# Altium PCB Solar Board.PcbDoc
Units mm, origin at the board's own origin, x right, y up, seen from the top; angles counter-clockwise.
Board outline 65 x 65 mm, 2 copper layers (Top Layer, Bottom Layer), stack 1.57 mm thick; 51 components, 34 nets, 176 pads, 29 vias.
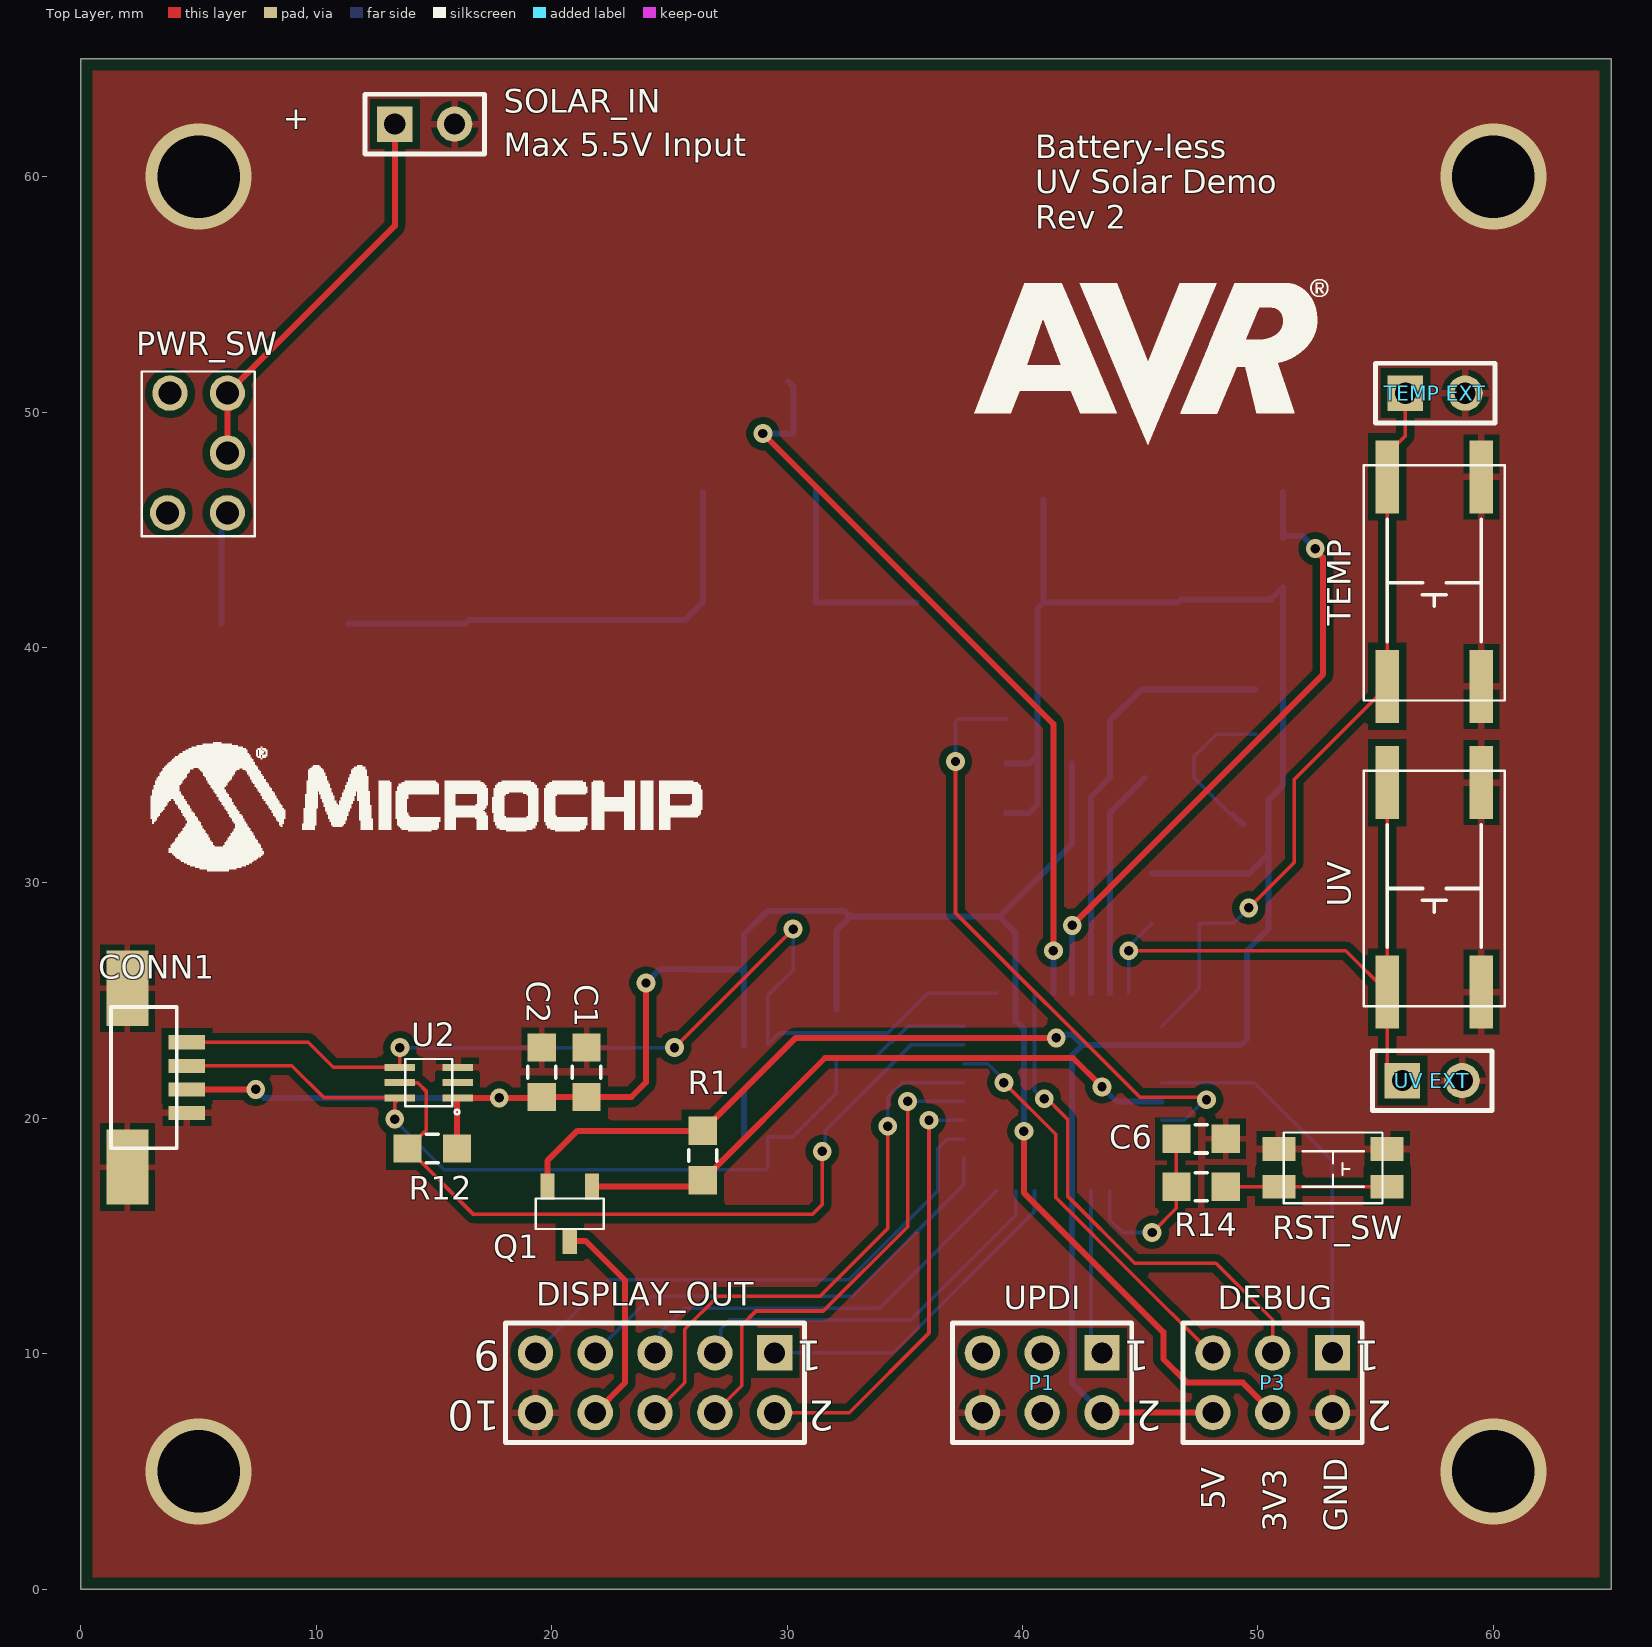
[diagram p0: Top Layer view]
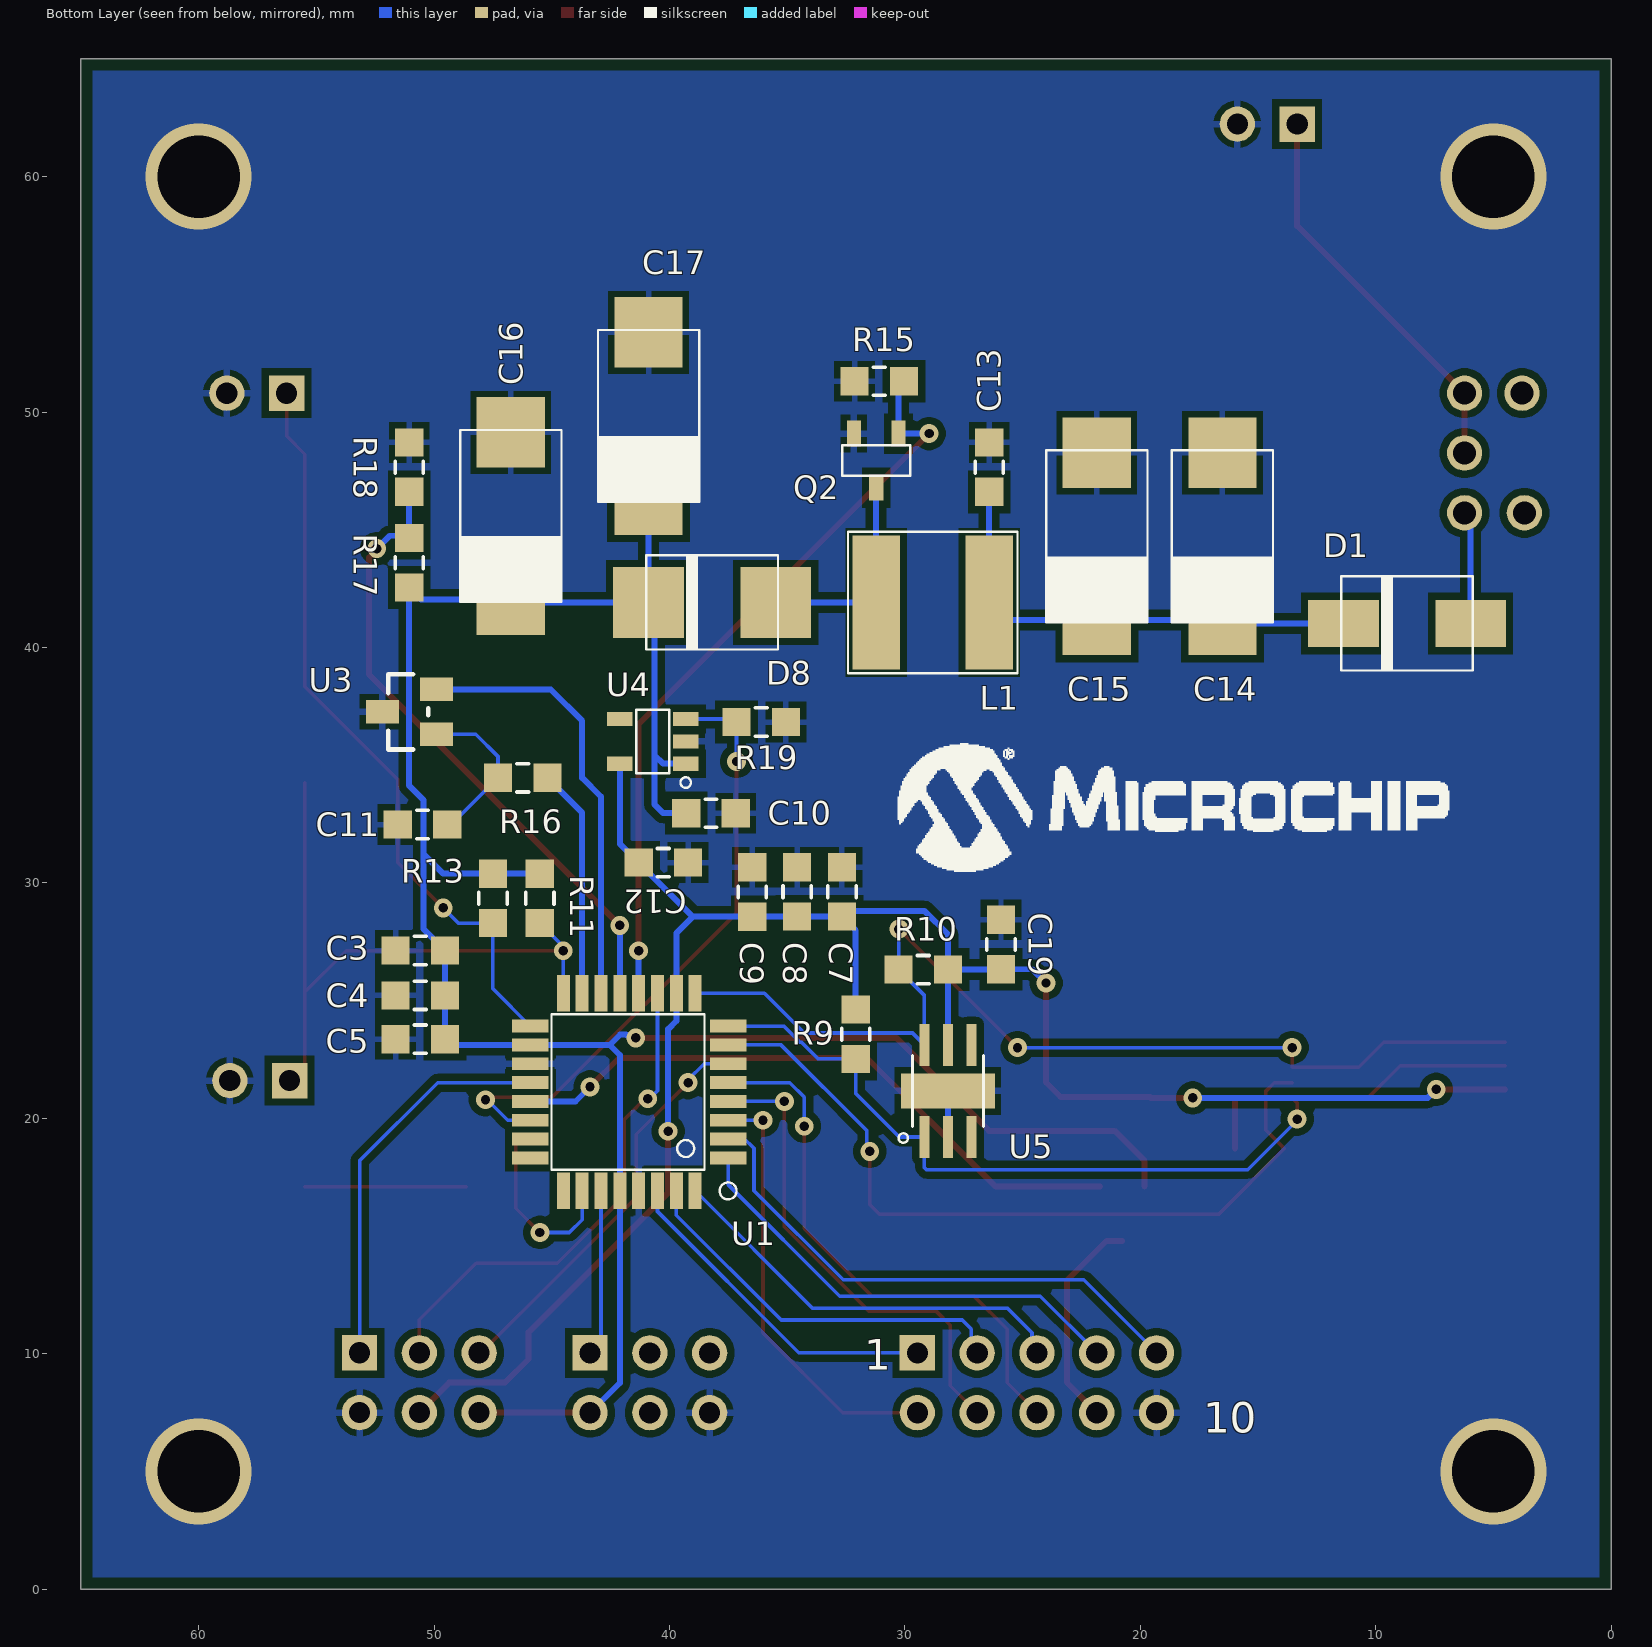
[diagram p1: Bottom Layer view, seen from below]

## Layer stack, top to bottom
Top Solder: solder mask 0.01, Solder Resist, Dk 3.5
Top Layer: signal copper 0.035
Dielectric1: core 1.5, FR-4, Dk 4.8
Bottom Layer: signal copper 0.035
Bottom Solder: solder mask 0.01, Solder Resist, Dk 3.5

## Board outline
0,0 0,65 65,65 65,0

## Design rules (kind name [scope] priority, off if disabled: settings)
AcuteAngle [All] p1 off: minimum=9.00000000000000E+0001 checktracksonly=TRUE
BoardOutlineClearance BoardOutlineClearance_Overlay [OnLayer('Top Overlay','Bottom Overlay')] p1: gap=0.2 ignorepadtopadclearanceinfootprint=FALSE
BoardOutlineClearance [All] p2: gap=0.5 ignorepadtopadclearanceinfootprint=FALSE
Clearance "Net to Polygon 0.5mm" [InNet('your net here') vs (IsRegion)] p1: gap=0.152 ignorepadtopadclearanceinfootprint=FALSE
Clearance "Poly 0.3mm" [(IsRegion)] p2: gap=0.3 ignorepadtopadclearanceinfootprint=FALSE
Clearance [All] p3: gap=0.25 ignorepadtopadclearanceinfootprint=TRUE
ComponentClearance ComponentClearance_ignore [HasFootprint('NET_TIE_0.5mm')] p1: gap=0 collisioncheckmode=3 verticalgap=0 showdistances=FALSE
ComponentClearance [All] p2: gap=0.2 collisioncheckmode=3 verticalgap=0.2 showdistances=FALSE
DiffPairsRouting [All] p1: maxlimit=0.25 minlimit=0.25 mostfreqgap=0.25 toplayer_minwidth=0.25 toplayer_maxwidth=0.25 toplayer_prefwidth=0.25 bottomlayer_minwidth=0.25 bottomlayer_maxwidth=0.25 bottomlayer_prefwidth=0.25 maxuncoupledlength=12.7
FabricationTestPointUsage TestPointUsage [All] p1: valid=0 allowmultiple=FALSE
FabricationTestpoint Testpoint [All] p1: side=3 testpointundercomponent=TRUE minsize=1.016 maxsize=2.54 preferedsize=1.524 minholesize=0 maxholesize=1.016 preferedholesize=0.813 testpointgrid=0.025 allowsidetop=TRUE allowsidebottom=TRUE usegrid=TRUE gridtolerance=0
HoleSize [All] p1: absolutevalues=TRUE maxlimit=6 minlimit=0.254 maxpercent=80.000 minpercent=20.000
HoleToHoleClearance [All] p1: gap=0.127 allowstackedmicrovias=FALSE
MinimumAnnularRing [All] p1: minimumring=0.127
MinimumSolderMaskSliver [All] p1: minsoldermaskwidth=0.102
PasteMaskExpansion PasteMaskExpansion_DNP [IsPad AND HasCompParameterValue('Populated','DNP')] p1: expansion=-5
PasteMaskExpansion [All] p2: expansion=0
PlaneClearance PlaneClearance_pads [IsPad] p1: clearance=0.3
PlaneClearance PlaneClearance_drill [IsObjectKind('Hole')] p2: clearance=0.4
PlaneConnect PlaneConnect_full [IsVia] p1: planeconnectstyle=Direct reliefexpansion=0.5 reliefentries=4 reliefconductorwidth=0.3 reliefairgap=0.3
PlaneConnect [All] p2: planeconnectstyle=Relief reliefexpansion=0.3 reliefentries=4 reliefconductorwidth=0.25 reliefairgap=0.25
PolygonConnect PolygonConnect_0.7 [IsNamedPolygon('0.7mm') vs (InPadClass('All Pads'))] p1: connectstyle=Relief reliefconductorwidth=0.7 reliefentries=4 polygonreliefangle="90 Angle" airgapwidth=0.25
PolygonConnect PolygonConnect_0.5 [IsNamedPolygon('0.5mm') vs (InPadClass('All Pads'))] p2: connectstyle=Relief reliefconductorwidth=0.5 reliefentries=4 polygonreliefangle="90 Angle" airgapwidth=0.25
PolygonConnect PolygonConnect_full [All vs IsVia or IsNamedPolygon('full')] p3: connectstyle=Direct reliefconductorwidth=0 reliefentries=4 polygonreliefangle="90 Angle" airgapwidth=0.254
PolygonConnect [All] p4: connectstyle=Relief reliefconductorwidth=0.3 reliefentries=4 polygonreliefangle="90 Angle" airgapwidth=0.25
RoutingCorners [All] p1: cornerstyle=45-Degree minsetback=2.5 maxsetback=2.5
RoutingVias [All] p1: holewidth=0.4 width=0.8 viastyle="Through Hole" minholewidth=0.3 minwidth=0.7 maxholewidth=1.6 maxwidth=2.5
SMDToCorner [All] p1: distance=39370
ShortCircuit [IsNet] p1: allowed=FALSE
SilkToSilkClearance [All] p1: silktosilkclearance=0.076
SilkToSolderMaskClearance SilkscreenOverComponentPads [IsPad] p1 off: minsilkscreentomaskgap=0.2 clearancetoexposedcopper=TRUE
SolderMaskExpansion SolderMaskExpansion_Component_Via [IsComponentVia] p1: expansion=0.075 istentingtop=FALSE soldermaskfromhole=TRUE
SolderMaskExpansion [All] p2: expansion=0.1 istentingtop=FALSE
UnRoutedNet [All] p1: checkbadconnections=TRUE
ViasUnderSMD [All] p1: allowed=FALSE
Width "Power Trace Width" [InNetClass('Power')] p1: maxlimit=7 minlimit=0.254 preferedwidth=0.254 minimp=50.000000 maximp=50.000000 favimp=50.000000
Width "Default Width" [InNetClass('All Nets')] p2: maxlimit=0.254 minlimit=0.152 preferedwidth=0.152 minimp=50.000000 maximp=50.000000 favimp=50.000000
15 further rules are at their usual default settings.

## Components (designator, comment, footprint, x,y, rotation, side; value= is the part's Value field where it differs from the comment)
C1 "Capacitor" 0805 21.479,20.901 r90 top
C2 "Capacitor" 0805 19.574,20.901 r90 top
C3 "Capacitor" 0805 49.535,27.125 r0 bottom
C4 "Capacitor" 0805 49.535,25.22 r0 bottom
C5 "Capacitor" 0805 49.535,23.361 r0 bottom
C6 "Capacitor" 0805 46.534,19.126 r0 top
C7 "Capacitor" 0805 32.673,28.567 r90 bottom
C8 "Capacitor" 0805 34.578,28.567 r90 bottom
C9 "Capacitor" 0805 36.483,28.561 r90 bottom
C10 "Capacitor" 0805 39.287,32.96 r180 bottom
C11 "Capacitor" 0805 49.439,32.477 r0 bottom
C12 "Capacitor" 0805 41.309,30.861 r180 bottom
C13 "Capacitor" 0805 26.416,46.609 r90 bottom
C14 "Polarized Capacitor" 2917 16.51,41.172 r90 bottom
C15 "Polarized Capacitor" 2917 21.844,41.172 r90 bottom
C16 "Polarized Capacitor" 2917 46.736,42.037 r90 bottom
C17 "Polarized Capacitor" 2917 40.887,46.286 r90 bottom
C19 "Capacitor" 0805 25.916,26.33 r90 bottom
CONN1 "STEMMA-QT" JST-ST 1.977,24.526 r270 top
D1 "Schottky" DO-215AB#1 5.969,41.021 r0 bottom
D8 "Schottky" DO-215AB#2 35.487,41.91 r0 bottom
DISPLAY_OUT "Header 5X2" HDR2X5 29.469,10.033 r180 top
L1 "Inductor" "6mm x 6mm Inductor" 26.416,41.91 r0 bottom value="330 uH"
P1 "Header 3X2" HDR2X3 43.373,10.033 r180 top
P3 "Header 3X2" HDR2X3 53.164,10.037 r180 top
PWR_SW "SPDT Slide" "CST11T2CR (SPST)" 3.683,45.72 r0 top
Q1 "PMOS Transistor" SOT-23 21.717,17.094 r180 top
Q2 "NMOS Transistor" SOT-23 30.266,49.086 r0 bottom
R1 "Resistor" 0805 26.416,17.367 r90 top value=100k
R9 "Resistor" 0805 32.089,22.52 r90 bottom value=10k
R10 "Resistor" 0805 30.269,26.315 r180 bottom value=10k
R11 "Resistor" 0805 45.505,30.391 r270 bottom value=DNP
R12 "Resistor" 0805 13.877,18.715 r0 top value=10k
R13 "Resistor" 0805 47.498,30.391 r270 bottom value=DNP
R14 "Resistor" 0805 46.534,17.094 r0 top value=330
R15 "Resistor" 0805 32.136,51.308 r180 bottom value=100k
R16 "Resistor" 0805 47.284,34.46 r180 bottom value=200
R17 "Resistor" 0805 51.054,44.645 r270 bottom value=100k
R18 "Resistor" 0805 51.054,48.709 r270 bottom value=10k
R19 "Resistor" 0805 35.052,36.83 r0 bottom value=100k
RST_SW "SPST Switch" KMR7 50.89,17.094 r0 top
SOLAR_IN "Header 2" HDR1X2 13.335,62.23 r0 top
TEMP "SPST Switch" KSC4 55.49,47.244 r270 top
"TEMP EXT" "Header 2" HDR1X2 56.261,50.8 r0 top
U1 "AVR64DD32" TQFP-32 37.509,18.315 r90 bottom
U2 "LTR390" "Extended QFN-6" 13.877,20.865 r90 top
U3 "MCP9700(A)_1(A) TO-92-3_SOT-23-3" SOT-23-3 51.047,37.265 r90 bottom value=MCP9700A
U4 "MCP1711" SOT23-5 39.309,35.06 r90 bottom
U5 "HTU21D(F) Humidity Sensor" "HTU21D(F) Extended Package" 28.169,21.16 r90 bottom
UV "SPST Switch" KSC4 55.49,34.26 r270 top
"UV EXT" "Header 2" HDR1X2 56.134,21.6 r0 top

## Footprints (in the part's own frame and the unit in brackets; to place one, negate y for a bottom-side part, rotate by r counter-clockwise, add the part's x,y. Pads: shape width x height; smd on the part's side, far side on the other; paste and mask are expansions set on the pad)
"6mm x 6mm Inductor" [mm] "For ASPI-6045S-331M-T"
  rect 2x5.7 smd: 1(0,0) 2(4.8,0)
  silkscreen extent -1.2,-3 6,3
0805 [mm] "Non-Polarized"
  rect 1.2x1.2 smd: 1(0,0) 2(2.1,0)
  silkscreen extent 0.8,-0.6 1.3,0.6
2917 [mm] "2917 SMD Package"
  rect 3x2.9 smd: A(0,0) K(7.1,0)
  silkscreen extent -0.1,-2.15 7.2,2.15
"CST11T2CR (SPST)" [mm] "SPST Switch Footprint for CST11T2CR"
  round 1.5 hole 0.98: 1(0,0) 3(0.1,5.08) 4(2.54,5.08) 5(2.54,2.54) 6(2.54,0)
  silkscreen extent -1.1,-1 3.7,6
DO-215AB#1 [mm]
  rect 3x2 smd: A(0,0) K(5.4,0)
  silkscreen extent -0.1,-2 5.5,2
DO-215AB#2 [mm]
  rect 3x3 smd: A(0,0) K(5.4,0)
  silkscreen extent -0.1,-2 5.5,2
"Extended QFN-6" [mm]
  rect 0.3x1.3 smd: 1(0,-2.125) 2(0.65,-2.125) 3(1.3,-2.125) 4(1.3,0.325) 5(0.65,0.325) 6(0,0.325)
  silkscreen extent -0.7,-2.2 1.65,0.1
HDR1X2 [mm] "Connector; Header; 2 Position"
  rect 1.5x1.5 hole 0.9: 1(0,0)
  round 1.5 hole 0.9: 2(2.54,0)
  silkscreen extent -1.27,-1.27 3.81,1.27
HDR2X3 [mm] "Connector; Header; 3x2 Position"
  rect 1.5x1.5 hole 0.9: 1(0,0)
  round 1.5 hole 0.9: 2(0,2.54) 3(2.54,0) 4(2.54,2.54) 5(5.08,0) 6(5.08,2.54)
  silkscreen extent -1.27,-1.27 6.35,3.81
HDR2X5 [mm] "Connector; Header; 5x2 Position"
  rect 1.5x1.5 hole 0.9: 1(0,0)
  round 1.5 hole 0.9: 2(0,2.54) 3(2.54,0) 4(2.54,2.54) 5(5.08,0) 6(5.08,2.54) 7(7.62,0) 8(7.62,2.54) 9(10.16,0) 10(10.16,2.54)
  silkscreen extent -1.27,-1.27 11.43,3.81
"HTU21D(F) Extended Package" [mm] "HTU21D(F) Humidity Sensor with Extended Pads"
  rrect11% 1.8x0.42 smd: 1(-1.955,1) 2(-1.955,0) 3(-1.955,-1) 4(1.955,-1) 5(1.955,0) 6(1.955,1)
  rect 1.5x4 smd paste-2: PAD(0,0)
  silkscreen extent -2.2,-1.5 1.5,2.1, body extent -1.5,-1.5 1.5,1.5, height 1
JST-ST [mm] "Stemma QT Connector"
  rect 0.6x1.55 smd: 1(4.3,2.525) 2(3.3,2.525) 3(2.3,2.525) 4(1.3,2.525)
  rect 3.2x1.8 smd: MECH1(-1,0) MECH2(6.6,0)
  silkscreen extent -0.2,-0.7 5.8,2.1
KMR7 [mm] "SPST Footprint for KMR7 Series SW"
  rect 1.4x1 smd: 1(4.6,1.6) 2(4.6,0) 3(0,0) 4(0,1.6)
  silkscreen extent 0.2,-0.7 4.4,2.3
KSC4 [mm] "Layout for KSC4 Series Pushbuttons (Ex: KSC421G 70SH LFS )"
  rect 3.1x1 smd: 1(0,4) 1(8.9,4) 2(0,0) 2(8.9,0)
  silkscreen extent -0.5,-1 9.5,5
SOT23-5 [mm]
  rect 0.6x1.1 smd: 1(0,0) 2(0.95,0) 3(1.9,0) 4(1.9,2.8) 5(0,2.8)
  silkscreen extent -1.02,-0.22 2.3,2.1
SOT-23 [mm]
  rect 0.6x1.1 smd: 1(0,0) 2(1.9,0) 3(0.95,2.3)
  silkscreen extent -0.5,0.5 2.4,1.8
SOT-23-3 [mm]
  rect 1x1.4 smd: 1(-0.95,-1.15) 2(0.95,-1.15) 3(0,1.15)
  silkscreen extent -1.6,-0.8 1.6,0.9, body extent -1.5,-1.25 1.5,1.25, height 1.09
TQFP-32 [mm]
  rect 0.55x1.55 smd: 1(0,0) 2(0.8,0) 3(1.6,0) 4(2.4,0) 5(3.2,0) 6(4,0) 7(4.8,0) 8(5.6,0) 17(5.6,8.4) 18(4.8,8.4) 19(4,8.4) 20(3.2,8.4) 21(2.4,8.4) 22(1.6,8.4) 23(0.8,8.4) 24(0,8.4)
  rect 1.55x0.55 smd: 9(7,1.4) 10(7,2.2) 11(7,3) 12(7,3.8) 13(7,4.6) 14(7,5.4) 15(7,6.2) 16(7,7) 25(-1.4,7) 26(-1.4,6.2) 27(-1.4,5.4) 28(-1.4,4.6) 29(-1.4,3.8) 30(-1.4,3) 31(-1.4,2.2) 32(-1.4,1.4)
  silkscreen extent -1.76,-0.36 6.1,7.5

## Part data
C1 C12: Capacitance=4.7uF
C2 C3 C7 C19: Capacitance=0.1uF
C4 C8: Capacitance=10nF
C5 C6 C9 C11: Capacitance=1uF
C10 C13: Capacitance=10uF
C14 C15 C16 C17: Capacitance=220uF, Rated Voltage=10V
CONN1: library part Stemma-QT, "Used with JST-ST Cables"
D1 D8: Part Number=LSM115JE3/TR13
DISPLAY_OUT: "Header, 5-Pin, Dual row"
L1: Part Number=ASPI-6045S-331M-T
P1 P3: "Header, 3-Pin, Dual row"
PWR_SW: Part Number=CST11T2CR
Q1: library part PMOS, Part Number=SSM3J168F,LF
Q2: library part NMOS, Part Number=DMN3731U-7
RST_SW TEMP UV: library part SPST
SOLAR_IN "TEMP EXT" "UV EXT": "Header, 2-Pin"
U3: library part MIC3211, "MCP97XX", Manufacturer 1=Microchip, Manufacturer Part Number 1=MCP9700AT-E/TT, Operating Temperature="-40C to +125C"
U4: Package=SOT23-5
U5: library part HTU21D

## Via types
v1: diameter 0.8, hole 0.4, Top Layer to Bottom Layer, 25 vias
v2: diameter 4.5, hole 3.5, Top Layer to Bottom Layer, 4 vias

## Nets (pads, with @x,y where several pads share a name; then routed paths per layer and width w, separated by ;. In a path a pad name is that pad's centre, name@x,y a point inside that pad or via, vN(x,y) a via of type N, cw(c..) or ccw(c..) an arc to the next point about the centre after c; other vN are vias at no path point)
"3.3V EN": R19.2 U1.22 U4.3 | length 26.6
  Top Layer w0.152: v1(37.152,35.155) 37.152,28.721 44.972,20.901 47.815,20.901 v1(47.815,20.789)
  Bottom Layer w0.152: v1(37.152,35.155) R19.2 37.282,36.96 U4.3 ; U1.22 46.867,19.915 47.74,20.789 v1(47.815,20.789)
+3.3: C1.1 C2.1 C7.1 C8.1 C9.1 C12.1 C19.1 CONN1.2 P3.4 R9.2 R10.2 R12.2 U1.10 U2.1 U4.5 U5.5 | length 87.8
  Top Layer w0.254: CONN1.2 v1(7.426,21.226) ; R12.2 15.977,20.84 U2.1 v1(17.77,20.865) 19.538,20.865 C2.1 C1.1 23.38,20.901 24.003,21.524 v1(24.003,25.744) ; v1(40.056,19.451) 40.056,16.84 45.984,10.912 45.984,9.772 46.99,8.766 49.355,8.766 P3.4
  Bottom Layer w0.254: v1(7.426,21.226) 7.788,20.865 v1(17.77,20.865) ; v1(24.003,25.744) 24.589,26.33 C19.1 25.931,26.315 R10.2 ; U5.5 R10.2 ; R9.2 32.089,27.983 C7.1 ; v1(40.056,19.451) 40.056,23.784 39.709,24.131 U1.10 39.709,27.861 39.009,28.561 ; U4.5 42.109,31.661 C12.1 39.009,28.561 ; R10.2 28.169,27.81 29.171,28.813 32.427,28.813 C7.1 ; C7.1 C8.1 36.477,28.567 C9.1 39.009,28.561
+5: C3.1 C4.1 C5.1 C10.1 C16.A C17.A D8.K P1.2 P3.6 Q1.2 R1.2 R11.1 R13.1 R17.2 U1.18 U1.28 U4.1 | length 106
  Top Layer w0.254: Q1.2 19.817,18.192 21.092,19.467 R1.2 30.363,23.414 v1(41.432,23.414) ; P1.2 43.376,7.497 P3.6
  Bottom Layer w0.254: C10.1 40.267,32.96 40.64,33.333 40.64,35.433 ; U4.1 40.267,35.06 40.64,35.433 ; C17.A D8.K ; v1(41.432,23.414) 41.536,23.519 41.812,23.519 41.854,23.56 42.091,23.56 42.537,23.115 ; P1.2 42.109,8.757 U1.28 42.109,22.687 42.537,23.115 ; R11.1 R13.1 49.608,30.391 50.454,31.237 ; 40.64,35.433 40.64,41.663 D8.K ; D8.K 46.609,41.91 C16.A 50.546,42.037 R17.2 51.054,34.126 50.454,33.526 50.454,31.237 ; 42.537,23.115 U1.18 49.289,23.115 C5.1 C4.1 C3.1 50.454,28.044 50.454,31.237
"DBG PD1": P3.3 U1.11 | length 21.6
  Top Layer w0.152: v1(40.925,20.826) 41.043,20.826 41.694,20.175 41.912,19.957 41.912,16.696 44.765,13.843 48.215,13.843 50.624,11.434 P3.3
  Bottom Layer w0.152: U1.11 40.509,21.173 40.856,20.826 v1(40.925,20.826)
"FET SW": Q2.1 R15.2 U1.12 | length 32.5
  Top Layer w0.25: v1(28.969,49.086) 41.309,36.746 v1(41.309,27.115)
  Bottom Layer w0.25: v1(28.969,49.086) Q2.1 30.266,51.078 R15.2 ; U1.12 v1(41.309,27.115)
GND: "TEMP EXT.2" "UV EXT.2" C1.2 C2.2 C3.2 C4.2 C5.2 C6.2 C7.2 C8.2 C9.2 C10.2 C11.2 C12.2 C13.2 C14.K C15.K C16.K C17.K C19.2 CONN1.1 CONN1.MECH1 CONN1.MECH2 DISPLAY_OUT.10 P1.6 P3.2 Q2.2 R15.1 R18.1 R19.1 RST_SW.1 RST_SW.4 SOLAR_IN.2 TEMP.1 U1.19 U1.29 U2.3 U3.3 U4.2 U5.2 U5.PAD UV.1 | length 2
  Bottom Layer w0.254: U5.2 U5.PAD
  other v2: 5,5 60,5 5,60 60,60
I\N\T\: R12.1 U1.7 U2.5 | length 33.6
  Top Layer w0.152: U2.5 14.302,21.515 14.677,21.14 14.677,19.515 R12.1 16.677,15.915 31.069,15.915 31.489,16.335 v1(31.489,18.594)
  Bottom Layer w0.152: v1(31.489,18.594) 31.611,18.716 31.611,19.467 35.258,23.115 U1.7
IO0: DISPLAY_OUT.1 U1.30 | length 14.4
  Bottom Layer w0.152: DISPLAY_OUT.1@29.461,10.033 34.502,10.033 40.509,16.04 U1.30
IO1: DISPLAY_OUT.3 U1.31 | length 16.7
  Bottom Layer w0.152: DISPLAY_OUT.3@26.921,10.033 DISPLAY_OUT.3@26.925,10.037 ; DISPLAY_OUT.3 27.179,10.284 27.179,11.046 27.563,11.43 35.253,11.43 39.709,15.886 U1.31
IO2: DISPLAY_OUT.5 U1.32 | length 17.7
  Bottom Layer w0.152: DISPLAY_OUT.5@24.381,10.033 24.599,10.251 24.599,10.883 25.654,11.938 33.932,11.938 U1.32
IO3: DISPLAY_OUT.7 U1.1 | length 19.8
  Bottom Layer w0.152: DISPLAY_OUT.7@21.841,10.033 24.254,12.446 32.766,12.446 37.509,17.189 U1.1
IO4: DISPLAY_OUT.9 U1.2 | length 23
  Bottom Layer w0.152: DISPLAY_OUT.9@19.301,10.033 22.404,13.136 32.617,13.136 36.408,16.926 36.408,18.725 36.599,18.916 36.609,18.916 36.808,19.115 U1.2
IO5: DISPLAY_OUT.2 U1.3 | length 18.5
  Top Layer w0.152: DISPLAY_OUT.2 32.639,7.493 36.027,10.881 v1(36.027,19.915)
  Bottom Layer w0.152: v1(36.027,19.915) U1.3
IO6: DISPLAY_OUT.4 U1.4 | length 20.7
  Top Layer w0.152: DISPLAY_OUT.4@26.921,7.493 28.067,8.639 28.067,11.201 28.677,11.811 31.538,11.811 35.117,15.39 v1(35.117,20.715)
  Bottom Layer w0.152: v1(35.117,20.715) U1.4
IO7: DISPLAY_OUT.6 U1.5 | length 23.5
  Top Layer w0.152: DISPLAY_OUT.6@24.381,7.493 25.654,8.766 25.654,11.041 27.059,12.446 31.399,12.446 34.273,15.32 v1(34.273,19.66)
  Bottom Layer w0.152: v1(34.273,19.66) 34.273,20.901 34.887,21.515 U1.5
"IO COM": Q1.1 R1.1 U1.21 | length 27.2
  Top Layer w0.254: Q1.1 26.143,17.094 R1.1 31.609,22.561 42.143,22.561 v1(43.373,21.331)
  Bottom Layer w0.254: v1(43.373,21.331) 43.989,20.715 U1.21
"LED Anode": DISPLAY_OUT.8 Q1.3 | length 9.2
  Top Layer w0.254: Q1.3 21.435,14.794 23.114,13.115 23.114,8.766 DISPLAY_OUT.8@21.841,7.493
NetC11_1: C11.1 R16.1 U3.1 | length 7.6
  Bottom Layer w0.152: C11.1@48.956,32.96 C11.1 49.267,32.477 R16.1 47.284,35.368 48.23,36.315 U3.1
NetC13_1: C13.1 C14.A C15.A D1.K L1.1 | length 20.1
  Bottom Layer w0.254: D1.K 16.359,41.021 C14.A C15.A 25.678,41.172 L1.1 C13.1
NetD1_A: D1.A PWR_SW.6 | length 4.8
  Bottom Layer w0.254: D1.A 5.969,45.129 6.223,45.383 PWR_SW.6
NetD8_A: D8.A L1.2 Q2.3 | length 9.1
  Bottom Layer w0.254: Q2.3 L1.2 D8.A
NetPWR_SW_COM: PWR_SW.4 PWR_SW.5 SOLAR_IN.1 | length 16.9
  Top Layer w0.254: PWR_SW.5 PWR_SW.4 13.335,57.912 SOLAR_IN.1
NetR14_2: R14.2 RST_SW.2 RST_SW.3 | length 6.9
  Top Layer w0.152: R14.2 RST_SW.3 RST_SW.2
"PWR FB": R17.1 R18.2 U1.13 | length 27
  Top Layer w0.254: v1(42.109,28.194) 52.759,38.844 52.759,43.812 52.435,44.136 v1(52.435,44.196)
  Bottom Layer w0.254: U1.13 v1(42.109,28.194) ; R18.2 R17.1 51.154,44.745 51.886,44.745 v1(52.435,44.196)
R\E\S\E\T\: C6.1 R14.1 U1.26 | length 7.6
  Top Layer w0.152: v1(45.505,15.149) 46.534,16.178 R14.1 C6.1
  Bottom Layer w0.152: U1.26 43.709,15.694 44.254,15.149 v1(45.505,15.149)
SCL: CONN1.4 R10.1 U1.9 U2.4 U5.6 | length 45.2
  Top Layer w0.152: CONN1.4 9.657,23.226 10.719,22.165 U2.4 v1(13.552,23.001) ; v1@25.23,22.987 v1(25.216,23.001) v1(30.251,28.036)
  Bottom Layer w0.152: v1(13.552,23.001) v1(25.216,23.001) ; v1(30.251,28.036) 30.251,26.333 R10.1 29.169,25.215 U5.6 29.677,23.623 34.273,23.623 35.965,25.315 U1.9
SDA: CONN1.3 R9.1 U1.8 U2.6 U5.1 | length 39.8
  Top Layer w0.152: CONN1.3 8.961,22.226 10.323,20.865 U2.6 13.335,20.648 v1(13.335,19.965)
  Bottom Layer w0.152: v1(13.335,19.965) 13.335,19.915 15.435,17.815 29.079,17.815 29.169,17.904 U5.1 30.241,19.205 32.089,21.053 R9.1 33.678,22.52 34.378,23.22 34.439,23.22 35.134,23.915 U1.8
"TCD-A Out (DBG)": P3.1 U1.20 | length 16.8
  Bottom Layer w0.152: U1.20 49.848,21.515 53.164,18.199 P3.1
"TEMP Button": "TEMP EXT.1" R13.2 TEMP.2 U1.17 | length 32
  Top Layer w0.152: v1(49.608,28.934) 51.539,30.865 51.539,34.393 55.49,38.344 55.49,47.244 55.49,48.21 56.261,48.981 56.261,50.8
  Bottom Layer w0.152: U1.17 47.498,25.504 R13.2 48.965,28.291 v1(49.608,28.934)
"TEMP IN": U1.14 U3.2 | length 18.6
  Bottom Layer w0.254: U1.14 42.909,33.659 43.709,34.459 43.709,36.882 45.042,38.215 U3.2
"TEMP PWR": R16.2 U1.15 | length 9.8
  Bottom Layer w0.254: U1.15 43.709,32.985 R16.2
"UART TX": P3.5 U1.6 | length 17.7
  Top Layer w0.152: v1(39.209,21.515) 41.409,19.315 41.409,16.63 41.42,16.63 41.51,16.541 41.51,16.529 44.598,13.441 48.002,10.037 P3.5 ; P3.5@48.292,10.291 P3.5@48.55,10.033
  Bottom Layer w0.152: U1.6 38.527,22.315 39.209,21.633 v1(39.209,21.515)
UPDI: P1.1 U1.27 | length 7.1
  Bottom Layer w0.152: U1.27 42.909,10.497 P1.1
"UV Button": "UV EXT.1" R11.2 U1.16 UV.2 | length 28
  Top Layer w0.152: v1(44.509,27.115) 53.735,27.115 UV.2@55.49,25.36 ; UV.2@55.49,34.26 UV.2@55.49,25.36 ; 56.134,21.6 55.49,22.244 UV.2@55.49,25.36
  Bottom Layer w0.152: U1.16 v1(44.509,27.115) 44.509,27.295 R11.2
pads on no net: P1.3 P1.4 P1.5 PWR_SW.1 PWR_SW.3 U1.23 U1.24 U1.25 U2.2 U4.4 U5.3 U5.4

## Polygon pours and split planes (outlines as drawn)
GND on Bottom Layer "GND_L02_P000" (solid, remove dead copper, pour order 0): 0,0 0,65 65,65 65,0
GND on Top Layer "GND_L01_P001" (solid, remove dead copper, pour order 1): 0,0 0,65 65,65 65,0

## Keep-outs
Keep-Out Layer:
  text "'.Layer_Name'" at 300.5,-158.75 h1.5

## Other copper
Top Layer:
  text "'.ProjectRevisionART'" at 335.678,-158.572 h1.5
  text "'.Layer_Name'" at 300.5,-158.75 h1.5
Bottom Layer:
  text "04-'.ProjectPCBNumber'-R'.ProjectRevisionART'" at 242,-108.5 h1.2
  text ".ProjectRevisionART" at 335.678,-158.572 h1.5
  text ".ProjectRevisionART" at 335.678,-158.572 h1.5
  text "'.ProjectRevisionART'" at 335.678,-158.572 h1.5
  text "'.Layer_Name'" at 300.5,-158.75 h1.5

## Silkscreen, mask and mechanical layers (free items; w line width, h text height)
Top Overlay:
  drawing of 21 lines, arcs and shapes, not listed
  text "+" at 8.582,62.009 h1
  text "Max 5.5V Input" at 17.96,60.858 h1
  text "Battery-less / UV Solar Demo / Rev 2" at 40.547,57.785 h1
  text "UPDI" at 39.209,11.884 h1
  text "DEBUG" at 48.284,11.884 h1
  text "5V" at 48.587,3.375 h1 r90
  text "3V3" at 51.2,2.432 h1 r90
  text "GND" at 53.8,2.432 h1 r90
  text "C" at 251.245,-112.043 h8
  text "1" at 260.096,-112.649 h5
  text "'.ProjectPartNumber'" at 231.5,-113 h1.2
  text "" at 244.245,-113.346 h8
  text "5" at 278.5,-114.194 h8
  text "7" at 288.5,-114.194 h8
  text "0" at 298.5,-114.194 h8
  text "1" at 308.5,-114.194 h8
  text "6" at 268.5,-114.227 h8
  text "2" at 318.5,-114.227 h8
  text "3" at 328.5,-114.227 h8
  text "4" at 338.58,-114.227 h8
  text "ICD" at 284.4,-122 h1.52
  text "M" at 262,-128.5 h10
  text "" at 315,-128.959 h10
  text "" at 294,-128.984 h10
  text "" at 305,-128.984 h10
  text "" at 324,-128.984 h10
  text "" at 335,-128.984 h10
  text "" at 346,-129.159 h10
  text "*h" at 227.7,-130 h7
  text "" at 286,-132 h10
  text "dsPICDEM.net™" at 185.75,-138.75 h3
  text "mTouch®" at 208,-138.75 h3
  text "chipKIT™" at 222.25,-138.75 h3
  text "dsPICDEM™" at 185.5,-144.5 h3
  text "MPLAB®" at 208,-145 h3
  text "dsPIC®" at 222.25,-145 h3
  text "PICDEM.net™" at 185.5,-150.75 h3
  text "PICkit™" at 208.25,-151 h3
  text "PIC®" at 222.25,-151 h3
  text "PICDEM™" at 185.5,-157.25 h3
  text "PICtail™" at 208.25,-157.25 h3
  text "'.ProjectRevisionART'" at 335.678,-158.572 h1.5
  text "'.Layer_Name'" at 300.5,-158.75 h1.5
Bottom Overlay:
  drawing of 15 lines, arcs and shapes, not listed
  text "1" at 31.719,9.326 h1.3
  text "10" at 17.318,6.643 h1.3
  text "'.ProjectRevisionART'" at 335.678,-158.572 h1.5
  text "'.Layer_Name'" at 300.5,-158.75 h1.5
Top Paste:
  text "'.ProjectRevisionART'" at 335.678,-158.572 h1.5
  text "'.Layer_Name'" at 300.5,-158.75 h1.5
Bottom Paste:
  text "'.ProjectRevisionART'" at 335.678,-158.572 h1.5
Top Solder:
  text "'.ProjectRevisionART'" at 335.678,-158.572 h1.5
  text "'.Layer_Name'" at 300.5,-158.75 h1.5
Bottom Solder:
  text "'.ProjectRevisionART'" at 335.678,-158.572 h1.5
NOTES (M1):
  text "ASSEMBLY NOTES:" at 29.4,-109.1 h4
  text "1. ALL COMPONENTS SHALL BE RoHS COMPLIANT." at -4.7,-114.2 h3
  text "2. ALL UNUSED THROUGH HOLE COMPONENT LOCATIONS SHALL BE FREE OF SOLDER." at -4.7,-117.2 h3
  text "3. ALL COMPONENTS SHALL BE MOUNTED FLUSH TO THE BOARD, EXCEPT AS NOTED." at -4.7,-120.2 h3
  text "4. FINISHED BOARD SHALL BE FREE OF ALL RESIDUES." at -4.7,-123.2 h3
  text "5. ALL LEADS SHALL BE TRIMMED TO A MAXIMUM HEIGHT OF 2mm" at -4.7,-126.2 h3
  text "'.Layer_Name'" at 318.5,-158.75 h1.5
BOARD (M2):
  the board outline again, w0.1
  text "'.ProjectRevisionART'" at 335.678,-158.572 h1.5
REF POINTS (M3):
  text "'.Layer_Name'" at 300.5,-158.75 h1.5
FAB (M4):
  drawing of 284 lines, arcs and shapes, not listed
  text "THIS PCB TO BE MANUFACTURED TO MEET ALL ACCEPTANCE LEVELS" at 236.989,51.662 h1.78
  text "OF A CLASS 2 PCB PER ANSI/IPC-A-600G." at 236.989,47.852 h1.78
  text "MATERIAL:" at 236.989,43.232 h1.78
  text "FR-4 or Equivalent" at 257.309,43.232 h1.78
  text "CONTROLLED IMPEDANCE" at 313.5,39 h1.78
  text "MULTILAYER" at 263.024,38.882 h1.78
  text "2" at 286.519,38.882 h1.78
  text "LAYERS" at 290.964,38.882 h1.78
  text "Cu WEIGHT EXTERNAL LAYERS" at 257.309,34.032 h1.78
  text "35um" at 309.379,34.032 h1.78
  text "FINISHED" at 318.904,34.032 h1.78
  text "Cu WEIGHT INTERNAL LAYERS" at 257.309,29.182 h1.78
  text "N/A" at 309.379,29.182 h1.78
  text "FINISHED" at 318.904,29.182 h1.78
  text "FINISHED OVERALL THICKNESS" at 257.309,24.332 h1.78
  text "1.6" at 310.649,24.332 h1.78
  text "mm" at 318.904,24.332 h1.78
  text "10" at 333.509,24.332 h1.78
  text "%" at 341.764,24.332 h1.78
  text "COPPER THIEVING ALLOWED" at 257.5,19.5 h1.78
  text "YES" at 314.5,19.5 h1.78
  text "NO" at 331.5,19.5 h1.78
  text "X" at 326.091,19 h2.6
  text "FINISH:" at 237,15 h1.78
  text "LEAD-FREE HOT AIR LEVELING" at 263,14.7 h1.78
  text "X" at 258.4,14 h2.6
  text "IMMERSION GOLD" at 263.024,9.162 h1.78
  text "IMMERSION TIN" at 263.024,3.662 h1.78
  text "SMOBC WITH SELECTIVE GOLD PLATING ON LANDS" at 263.024,-0.043 h1.78
  text "INDICATED. 1um GOLD OVER 5-10 um NICKEL" at 263.024,-3.853 h1.78
  text "SOLDERMASK" at 257.309,-9.188 h1.78
  text "DYNACHEM EPIC 200 LPI OR EQUIVALENT" at 278.899,-9.188 h1.78
  text "SOLDERMASK COLOR" at 257.309,-15.538 h1.78
  text "GREEN HIGH GLOSS" at 289.059,-15.538 h1.78
  text "SILKSCREEN COLOR" at 257.309,-21.888 h1.78
  text "WHITE" at 289.059,-21.888 h1.78
  text "Blind / Burried Vias" at 263.5,-28 h1.78
  text "DRILLING:" at 237.5,-28.25 h1.78
  text "Via Layer Pairs" at 258,-32.75 h1.78
  text "Top-Bottom" at 278.75,-32.75 h1.78
  text "ALL HOLES TO BE LOCATED BY THE COORDINATES FROM THE NC DRILL DATA PROVIDED." at 236.989,-38 h1.78
  text "05-'.ProjectPCBNumber'" at 269,-44.5 h1.78
  text "PCB REV" at 305,-44.5 h1.78
  text "USE ARTWORK SET NO." at 236.989,-44.588 h1.78
  text "'.ProjectRevisionART'" at 318.15,-44.75 h1.78
  text "ALL UL LOGO, MANUFACTURER'S ID, AND DATE CODES SHALL BE PLACED" at 236.989,-50.938 h1.78
  text "ON THE BOTTOM SIDE UNLESS OTHERWISE INDICATED." at 236.989,-54.748 h1.78
  text "ANY ALTERNATIVES TO THE ABOVE SPECIFICATIONS MUST FIRST BE APPROVED." at 236.5,-60 h1.78
  text "Layer" at 224.029,-66.675 h1.52
  text "Name" at 234.441,-66.675 h1.52
  text "Material" at 258.056,-66.675 h1.52
  text "Thickness" at 279.894,-66.675 h1.52
  text "Constant" at 296.4,-66.675 h1.52
  text "Gerber" at 310.875,-66.675 h1.52
  text "Board Layer Stack" at 322.81,-66.675 h1.52
  text "Top Overlay" at 234.441,-69.723 h1.52
  text "GTO" at 310.875,-69.723 h1.52
  text "Top Solder" at 234.441,-72.771 h1.52
  text "Solder Resist" at 258.056,-72.771 h1.52
  text "0.010mm" at 279.894,-72.771 h1.52
  text "3.5" at 296.4,-72.771 h1.52
  text "GTS" at 310.875,-72.771 h1.52
  text "1" at 224.029,-75.819 h1.52
  text "Top Layer" at 234.441,-75.819 h1.52
  text "0.035mm" at 279.894,-75.819 h1.52
  text "GTL" at 310.875,-75.819 h1.52
  text "Dielectric1" at 234.441,-78.867 h1.52
  text "FR-4" at 258.056,-78.867 h1.52
  text "1.500mm" at 279.894,-78.867 h1.52
  text "4.8" at 296.4,-78.867 h1.52
  text "2" at 224.029,-81.915 h1.52
  text "Bottom Layer" at 234.441,-81.915 h1.52
  text "0.035mm" at 279.894,-81.915 h1.52
  text "GBL" at 310.875,-81.915 h1.52
  text "Bottom Solder" at 234.441,-84.963 h1.52
  text "Solder Resist" at 258.056,-84.963 h1.52
  text "0.010mm" at 279.894,-84.963 h1.52
  text "3.5" at 296.4,-84.963 h1.52
  text "GBS" at 310.875,-84.963 h1.52
  text "Bottom Overlay" at 234.441,-88.011 h1.52
  text "GBO" at 310.875,-88.011 h1.52
  text "Total board thickness:" at 224.029,-91.059 h1.52
  text "1.590mm" at 279.894,-91.059 h1.52
  text "'.ProjectRevisionFAB'" at 335.678,-158.572 h1.5
  text "'.Layer_Name'" at 300.5,-158.75 h1.5
Case (M5):
  text "'.Layer_Name'" at 300.5,-158.75 h1.5
Cover (M6):
  text "'.Layer_Name'" at 300.5,-158.75 h1.5
Terminal Block (M7):
  text "'.Layer_Name'" at 300.5,-158.75 h1.5
V-Cut (M9):
  text "'.Layer_Name'" at 300.5,-158.75 h1.5
Bottom Assembly:
  text "'.VariantName'" at 50.07,-142.75 h0.9
  text "ASSEMBLY VARIANT:" at 64.32,-142.75 h0.9
  text "DOCUMENT NUMBER:" at 18.05,-151 h1.14
  text "02-'.ProjectPCBAssyNumber'-D" at 17.8,-154 h1.6
  text "'.ProjectRevisionASSY'" at 1.122,-158.572 h1.5
  text "'.Layer_Name'" at 36,-158.75 h1
Top Assembly:
  text "6. PLACE LABEL  ON THE LOCATION INDICATED." at -4.7,-129.2 h3
  text "7." at -4.7,-132.2 h3
  text "ASSEMBLY VARIANT:" at 272.5,-142.75 h0.9
  text "'.VariantName'" at 286.75,-142.75 h0.9
  text "DOCUMENT NUMBER:" at 318.75,-151 h1.15
  text "02-'.ProjectPCBAssyNumber'-D" at 319,-154 h1.6
  text "'.ProjectRevisionASSY'" at 335.678,-158.572 h1.5
Bottom Courtyard:
  text ".ProjectRevisionART" at 335.678,-158.572 h1.5
Top Courtyard:
  text "'.ProjectRevisionART'" at 335.678,-158.572 h1.5
TITLE (M16):
  lines w0.1: 272,-141.5 353.82,-141.5 ; 324,-134 324,-137 353.82,-137 ; 342.54,-158.635 342.54,-157.365 ; 342.54,-158 352.7,-158 ; 342.7,-156.8 342.7,-155.8 ; 342.7,-156.3 352.7,-156.3 ; 345.08,-158.635 345.08,-157.365 ; 347.62,-158.635 347.62,-157.365 ; 347.7,-156.6 347.7,-156 ; 350.16,-158.635 350.16,-157.365 ; 352.7,-158.635 352.7,-157.365 ; 352.7,-156.8 352.7,-155.8 ; 353.82,-137 353.82,-137
  lines w0.127: -22.1,-104.175 -17.02,-104.175 ; -22.1,-43.85 -17.02,-43.85 ; -22.1,16.475 -17.02,16.475 ; 41.4,-164.5 41.4,-159.42 ; 41.4,71.72 41.4,76.8 ; 104.9,-164.5 104.9,-159.42 ; 104.9,71.72 104.9,76.8 ; 168.4,-164.5 168.4,-159.42 ; 168.4,71.72 168.4,76.8 ; 203.96,-159.42 239.52,-159.42 ; 231.9,-164.5 231.9,-159.42 ; 231.9,71.72 231.9,76.8 ; 272,-159.42 272,-134 ; 272,-155 353.82,-155 ; 272,-149 353.82,-149 ; 272,-143 353.82,-143 ; 295.4,-164.5 295.4,-159.42 ; 295.4,71.72 295.4,76.8 ; 300,-159.42 300,-143 ; 318,-155 318,-149 ; 331,-159.42 331,-155 ; 338.5,-159.42 338.5,-149 ; 353.82,-128.94 353.82,-159.42 ; 353.82,-104.175 358.9,-104.175 ; 353.82,-43.85 358.9,-43.85 ; 353.82,16.475 358.9,16.475 ; 353.82,-159.42 353.82,-134 238,-134 238,-159.42 353.82,-159.42 ; 353.82,-159.42 -17.02,-159.42 -17.02,71.72 353.82,71.72 353.82,-159.42 ; -22.1,-164.5 358.9,-164.5 358.9,76.8 -22.1,76.8 -22.1,-164.5
  lines w0.254: 243.32,62.72 243.32,67.22 243.32,71.72 ; 255.82,62.72 255.82,67.22 255.82,71.72 ; 334.32,62.72 334.32,67.22 334.32,71.72 ; 353.82,67.22 232.32,67.22 ; 232.32,67.22 232.32,71.72 353.82,71.72 353.82,62.72 232.32,62.72 232.32,67.22
  text "1" at 9.176,73.498 h1.78
  text "2" at 72.566,73.498 h1.78
  text "3" at 135.795,73.498 h1.78
  text "4" at 199.464,73.498 h1.78
  text "5" at 262.939,73.498 h1.78
  text "6" at 326.566,73.498 h1.78
  text "REV" at 234.82,68.72 h1.52
  text "ECO" at 244.82,68.72 h1.52
  text "Comments" at 291.32,68.22 h1.52
  text "Date" at 339.32,68.22 h1.52
  text "A" at -20.195,44.466 h1.78
  text "A" at 355.725,44.466 h1.78
  text "B" at -20.195,-15.986 h1.78
  text "B" at 355.725,-15.986 h1.78
  text "C" at -20.195,-76.311 h1.78
  text "C" at 355.725,-76.311 h1.78
  text "PART NUMBER:" at 325,-136 h1
  text "'.ProjectpartNumber'" at 337,-136.25 h1.5
  text "D" at -20.195,-136.509 h1.78
  text "TITLE:" at 273,-136.5 h1.14
  text "D" at 355.725,-136.509 h1.78
  text "'.ProjectTitle'" at 273,-140.5 h2.5
  text "PCB Layout Contact:" at 273,-145 h1.15
  text "GERBER FILE:" at 301,-145 h1.15
  text "'.ProjectDrawnBy'" at 273,-148 h1.6
  text "'.Plot_File_Name'" at 301,-148 h1.5
  text "M" at 241,-150 h15.24
  text "Project Owner:" at 273,-151 h1.15
  text "BOARD NUMBER:" at 301,-151 h1.15
  text "DATE:" at 339.7,-151 h1.14
  text "Microchip Technology Inc." at 239.77,-153.26 h1.78
  text "'.ProjectEngineer'" at 273,-154 h1.6
  text "04-'.ProjectPCBNumber'" at 301,-154 h1.6
  text "'.PRINT_DATE'" at 339.7,-154 h1.5
  text "2355 W. Chandler Blvd." at 241,-156 h1.78
  text "LAYER NAME:" at 301,-156.5 h1.14
  text "10mm" at 339,-156.6 h0.7
  text "PCB FILE NAME:" at 273,-156.75 h1.15
  text "REV:" at 331.75,-156.75 h1.14
  text "400mil" at 338.9,-158.3 h0.7
  text "Chandler, AZ  85224" at 242,-158.5 h1.78
  text "'.PCB_FILE_NAME_NO_PATH'" at 273,-158.75 h1
  text "1" at 9.176,-162.722 h1.78
  text "2" at 72.566,-162.722 h1.78
  text "3" at 135.795,-162.722 h1.78
  text "4" at 199.464,-162.722 h1.78
  text "5" at 262.939,-162.722 h1.78
  text "6" at 326.566,-162.722 h1.78
Drill Drawing:
  circle w0.25: c-5.348,-75.095 r0.833
  lines w0.25: -6.181,-83.429 -4.514,-83.429 -4.514,-81.762 -6.181,-81.762 -6.181,-83.429 ; -6.181,-78.012 -4.514,-78.012 -5.348,-79.679 -6.181,-78.012 ; -6.181,-71.762 -5.764,-71.762 -5.348,-72.179 -4.931,-71.762 -4.514,-71.762 -4.931,-71.345 -4.514,-70.929 -4.931,-70.929 -5.348,-70.512 -5.764,-70.929 -6.181,-70.929 -5.764,-71.345 -6.181,-71.762
  lines w0.3: -7.676,-84.554 197.117,-84.554 ; -7.676,-69.554 197.117,-69.554 ; 6.096,-88.304 6.096,-65.804 ; 23.541,-88.304 23.541,-65.804 ; 57.182,-88.304 57.182,-65.804 ; 69.828,-88.304 69.828,-65.804 ; 107.317,-88.304 107.317,-65.804 ; 122.063,-88.304 122.063,-65.804 ; 140.408,-88.304 140.408,-65.804 ; 162.052,-88.304 162.052,-65.804 ; -7.676,-88.304 197.117,-88.304 197.117,-65.804 -7.676,-65.804 -7.676,-88.304
  text "Symbol" at -5.426,-68.429 h1.8
  text "Hit Count" at 7.221,-68.429 h1.8
  text "Finished Hole Size" at 24.666,-68.429 h1.8
  text "Plated" at 58.307,-68.429 h1.8
  text "Drill Layer Pair" at 70.953,-68.429 h1.8
  text "Via/Pad" at 108.442,-68.429 h1.8
  text "Hole Type" at 123.188,-68.429 h1.8
  text "Hole Length" at 141.533,-68.429 h1.8
  text "Routed Path Length" at 163.177,-68.429 h1.8
  text "4" at 7.221,-72.179 h1.5
  text "3.500mm (137.79mil)" at 24.666,-72.179 h1.5
  text "PTH" at 58.307,-72.179 h1.5
  text "Top Layer - Bottom Layer" at 70.953,-72.179 h1.5
  text "Via" at 108.442,-72.179 h1.5
  text "Round" at 123.188,-72.179 h1.5
  text "-" at 141.533,-72.179 h1.5
  text "-" at 163.177,-72.179 h1.5
  text "5" at 7.221,-75.929 h1.5
  text "0.980mm (38.58mil)" at 24.666,-75.929 h1.5
  text "PTH" at 58.307,-75.929 h1.5
  text "Top Layer - Bottom Layer" at 70.953,-75.929 h1.5
  text "Pad" at 108.442,-75.929 h1.5
  text "Round" at 123.188,-75.929 h1.5
  text "-" at 141.533,-75.929 h1.5
  text "-" at 163.177,-75.929 h1.5
  text "25" at 7.221,-79.679 h1.5
  text "0.400mm (15.75mil)" at 24.666,-79.679 h1.5
  text "PTH" at 58.307,-79.679 h1.5
  text "Top Layer - Bottom Layer" at 70.953,-79.679 h1.5
  text "Via" at 108.442,-79.679 h1.5
  text "Round" at 123.188,-79.679 h1.5
  text "-" at 141.533,-79.679 h1.5
  text "-" at 163.177,-79.679 h1.5
  text "28" at 7.221,-83.429 h1.5
  text "0.900mm (35.43mil)" at 24.666,-83.429 h1.5
  text "PTH" at 58.307,-83.429 h1.5
  text "Top Layer - Bottom Layer" at 70.953,-83.429 h1.5
  text "Pad" at 108.442,-83.429 h1.5
  text "Round" at 123.188,-83.429 h1.5
  text "-" at 141.533,-83.429 h1.5
  text "-" at 163.177,-83.429 h1.5
  text "62 Total" at 7.221,-87.179 h1.5
  text "DOCUMENT NUMBER:" at 318.75,-151 h1.15
  text "04-'.ProjectPCBNumber'-D" at 319,-154 h1.6
  text "'.ProjectRevisionFAB'" at 335.678,-158.572 h1.5
TITLE MIRROR (M17):
  lines w0.1: -15.9,-158.635 -15.9,-157.365 ; -15.9,-158 -5.74,-158 ; -15.9,-156.8 -15.9,-155.8 ; -15.9,-156.3 -5.9,-156.3 ; -13.36,-158.635 -13.36,-157.365 ; -10.9,-156.6 -10.9,-156 ; -10.82,-158.635 -10.82,-157.365 ; -8.28,-158.635 -8.28,-157.365 ; -5.9,-156.8 -5.9,-155.8 ; -5.74,-158.635 -5.74,-157.365
  lines w0.127: -22.1,-104.175 -17.02,-104.175 ; -22.1,-43.85 -17.02,-43.85 ; -22.1,16.475 -17.02,16.475 ; -17.02,-155 64.8,-155 ; -17.02,-149 64.8,-149 ; -17,-143 64.82,-143 ; -17,-141.5 64.82,-141.5 ; -17,-137 -16.383,-137 ; -1.7,-159.42 -1.7,-149 ; 5.8,-159.42 5.8,-155 ; 12.82,-134 12.82,-137 -16.383,-137 ; 18.8,-155 18.8,-149 ; 36.82,-159.42 36.82,-143 ; 41.4,-164.5 41.4,-159.42 ; 41.4,71.72 41.4,76.8 ; 64.82,-159.42 64.82,-134 ; 104.9,-164.5 104.9,-159.42 ; 104.9,71.72 104.9,76.8 ; 168.4,-164.5 168.4,-159.42 ; 168.4,71.72 168.4,76.8 ; 231.9,-164.5 231.9,-159.42 ; 231.9,71.72 231.9,76.8 ; 295.4,-164.5 295.4,-159.42 ; 295.4,71.72 295.4,76.8 ; 353.82,-104.175 358.9,-104.175 ; 353.82,-43.85 358.9,-43.85 ; 353.82,16.475 358.9,16.475 ; -17.02,-159.42 98.82,-159.42 98.82,-134 -17.02,-134 -17.02,-159.42 ; -17.02,-159.42 -17.02,71.72 353.82,71.72 353.82,-159.42 -17.02,-159.42 ; -16.383,-137 -16.383,-137 ; -22.1,-164.5 -22.1,76.8 358.9,76.8 358.9,-164.5 -22.1,-164.5
  text "6" at 10.234,73.498 h1.78
  text "5" at 73.861,73.498 h1.78
  text "4" at 137.336,73.498 h1.78
  text "3" at 201.005,73.498 h1.78
  text "2" at 264.234,73.498 h1.78
  text "1" at 327.624,73.498 h1.78
  text "A" at -18.925,44.466 h1.78
  text "A" at 356.995,44.466 h1.78
  text "B" at -18.925,-15.986 h1.78
  text "B" at 356.995,-15.986 h1.78
  text "C" at -18.925,-76.311 h1.78
  text "C" at 356.995,-76.311 h1.78
  text "PART NUMBER:" at 11.82,-136 h1
  text "TITLE:" at 63.82,-136 h1.14
  text "'.ProjectpartNumber'" at -0.18,-136.25 h1.5
  text "D" at -18.925,-136.509 h1.78
  text "D" at 356.995,-136.509 h1.78
  text "'.ProjectTitle'" at 63.82,-140.5 h2.5
  text "GERBER FILE:" at 35.82,-145 h1.14
  text "PCB DESIGNER:" at 63.82,-145 h1.14
  text "'.Plot_File_Name'" at 35.82,-148 h1.5
  text "'.ProjectDrawnBy'" at 63.82,-148 h1.78
  text "M" at 95.82,-150 h15.24
  text "DATE:" at -2.9,-151 h1.14
  text "BOARD NUMBER:" at 35.8,-151 h1.14
  text "ENGINEER:" at 63.8,-151 h1.14
  text "Microchip Technology Inc." at 97.05,-153.26 h1.78
  text "'.PRINT_DATE'" at -2.9,-154 h1.5
  text "04-'.ProjectPCBNumber'" at 35.8,-154 h1.6
  text "'.ProjectEngineer'" at 63.8,-154 h1.78
  text "2355 W. Chandler Blvd." at 95.82,-156 h1.78
  text "LAYER NAME:" at 35.8,-156.5 h1.14
  text "10mm" at -2.2,-156.6 h0.7
  text "REV:" at 5.05,-156.75 h1.14
  text "PCB FILE NAME:" at 63.8,-156.75 h1.14
  text "400mil" at -2.1,-158.3 h0.7
  text "Chandler, AZ  85224" at 94.82,-158.5 h1.78
  text "'.PCB_FILE_NAME_NO_PATH'" at 63.8,-158.75 h1.14
  text "6" at 10.234,-162.722 h1.78
  text "5" at 73.861,-162.722 h1.78
  text "4" at 137.336,-162.722 h1.78
  text "3" at 201.005,-162.722 h1.78
  text "2" at 264.234,-162.722 h1.78
  text "1" at 327.624,-162.722 h1.78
